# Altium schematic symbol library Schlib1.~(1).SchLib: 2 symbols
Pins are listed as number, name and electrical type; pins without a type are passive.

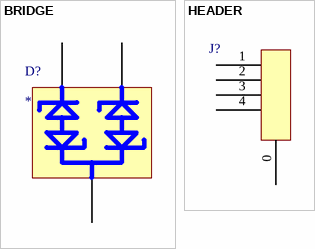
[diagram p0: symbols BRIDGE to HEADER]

## BRIDGE
designator D?
pins: 1, 2, 3

## HEADER
designator J?  (value not drawn)
pins: 0, 1, 2, 3, 4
